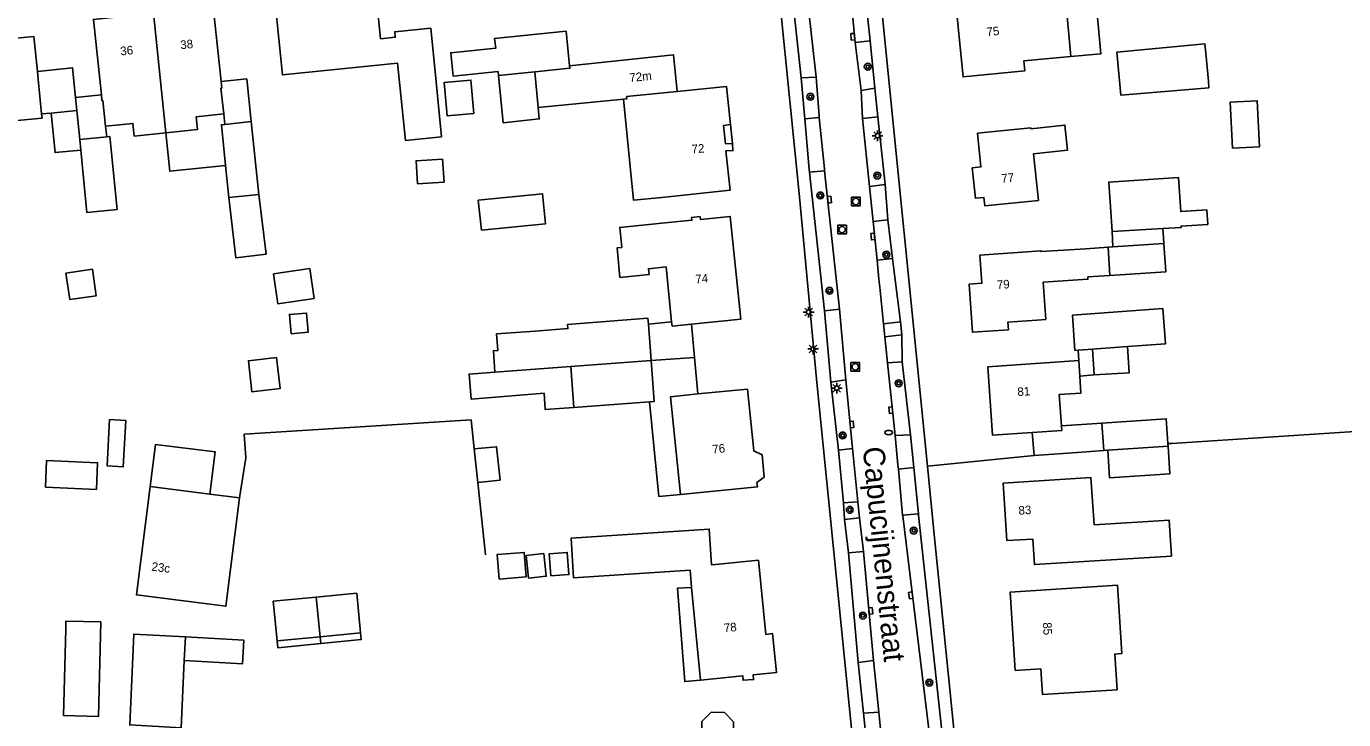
# Model space of a CAD drawing. Extents: x 140000 to 143000, y 403500 to 406000.
# Drawn here: x 140499.7 to 140652.7, y 403593.5 to 403674.1 of the extents above; entities that cross this region are included whole.
import ezdxf

# ---------------------------------------------------------------- set-up
doc = ezdxf.new("R2010")
doc.units = 0
for name, color, linetype in [('gg-afsc-erfafscheiding', 7, 'Continuous'), ('gg-afsc-hekwerk', 7, 'Continuous'), ('gg-anno-huisnummerreeks BGT', 7, 'Continuous'), ('gg-anno-openbare ruimte label', 7, 'Continuous'), ('gg-bbg-bijgebouw', 7, 'Continuous'), ('gg-bbg-gedigitaliseerde bebouwing', 7, 'Continuous'), ('gg-bbg-gedigitaliseerde bijgebouw', 7, 'Continuous'), ('gg-bbg-hoofdgebouw', 7, 'Continuous'), ('gg-bbg-luifel en loopbrug', 7, 'Continuous'), ('gg-bbg-overig bouwwerk', 7, 'Continuous'), ('gg-bbg-tussenscheiding', 7, 'Continuous'), ('gg-knt-verharding', 7, 'Continuous'), ('gg-knt-verharding nz', 7, 'Continuous'), ('gt-symb-boom', 7, 'Continuous'), ('gt-symb-brandkraan', 7, 'Continuous'), ('gt-symb-kolk', 7, 'Continuous'), ('gt-symb-lichtmast', 7, 'Continuous'), ('gt-symb-rioolschacht', 7, 'Continuous')]:
    doc.layers.add(name, color=color, linetype=linetype)

# ---------------------------------------------------------------- blocks, each defined once
blk = doc.blocks.new('gt0-KOLK')
at = {"layer": 'gt-symb-kolk'}
blk.add_lwpolyline([(0, 0), (0.38, 0), (0.38, 0.4), (-0.37, 0.4), (-0.37, 0), (0, 0)], dxfattribs=at)
blk = doc.blocks.new('gt0-BR')
at = {"layer": 'gt-symb-brandkraan'}
for centre, radius, start, end in [((-0.24, 0), 0.206, 107.5669, 252.4331), ((0.6, -2.66), 3, 106.892, 107.5669), ((0, -0.69), 0.938, 73.108, 106.892), ((-0.6, -2.66), 3, 72.4331, 73.108), ((0.24, 0), 0.206, 287.567, 72.4331), ((0.6, 2.66), 3, 252.4331, 253.108), ((0, 0.69), 0.938, 253.108, 286.8921), ((-0.6, 2.66), 3, 286.8921, 287.567)]:
    blk.add_arc(centre, radius, start, end, dxfattribs=at)
blk = doc.blocks.new('gt0-LMAST')
at = {"layer": 'gt-symb-lichtmast'}
for p, q in [((-0.18, 0.17), (-0.45, 0.44)), ((-0.01, 0.25), (-0.01, 0.62)), ((0.17, 0.17), (0.44, 0.44)), ((-0.26, 0), (-0.63, 0)), ((-0.18, -0.18), (-0.45, -0.45)), ((-0.01, -0.25), (-0.01, -0.63)), ((0.44, -0.45), (0.17, -0.18)), ((0.24, 0), (0.62, 0))]:
    blk.add_line(p, q, dxfattribs=at)
blk.add_circle((-0.01, 0), 0.25, dxfattribs=at)
blk = doc.blocks.new('gt0-BOOM')
at = {"layer": 'gt-symb-boom'}
for radius in [0.4, 0.2]:
    blk.add_circle((0, 0), radius, dxfattribs=at)
blk = doc.blocks.new('gt0-RS')
at = {"layer": 'gt-symb-rioolschacht'}
blk.add_lwpolyline([(-0.5, -0.5), (0.5, -0.5), (0.5, 0.5), (-0.5, 0.5)], close=True, dxfattribs=at)
blk.add_circle((0, 0), 0.375, dxfattribs=at)

msp = doc.modelspace()

# ---------------------------------------------------------------- linework, layer by layer
at = {"layer": 'gg-afsc-erfafscheiding'}
for p, q in [((140616.75, 403624.23), (140604.37, 403622.98)), ((140607.14, 403595.14), (140611, 403556.5))]:
    msp.add_line(p, q, dxfattribs=at)
for points in [[(140524.47, 403619.29), (140525.2, 403623.94), (140525, 403626.69), (140551.38, 403628.34)], [(140658.72, 403627.3), (140632.76, 403625.62), (140632.3, 403625.6)], [(140604.37, 403622.98), (140605.16, 403615.02), (140607.14, 403595.14)]]:
    msp.add_lwpolyline(points, dxfattribs=at)
at = {"layer": 'gg-afsc-hekwerk'}
for p, q in [((140551.38, 403628.34), (140551.73, 403624.97)), ((140552.13, 403621.09), (140553.01, 403612.66))]:
    msp.add_line(p, q, dxfattribs=at)
at = {"layer": 'gg-bbg-bijgebouw'}
for p, q in [((140554.53, 403668.36), (140558.74, 403668.79)), ((140505.56, 403664.3), (140502.58, 403664.01)), ((140505.9, 403660.93), (140505.56, 403664.3)), ((140525.82, 403663.01), (140522.75, 403662.68)), ((140526.71, 403654.56), (140525.82, 403663.01)), ((140505.9, 403660.93), (140509.03, 403661.24)), ((140523.23, 403654.2), (140522.84, 403657.92)), ((140523.23, 403654.2), (140526.71, 403654.56)), ((140625.8, 403650.25), (140625.91, 403648.45)), ((140631.82, 403648.84), (140625.91, 403648.45)), ((140572.27, 403635.26), (140571.95, 403639.46)), ((140627.59, 403636.87), (140623.54, 403636.57)), ((140562.93, 403634.56), (140554.12, 403633.89)), ((140562.93, 403634.56), (140563.29, 403629.79)), ((140563.29, 403629.79), (140572.08, 403630.46)), ((140624.85, 403624.81), (140624.63, 403627.98)), ((140624.85, 403624.81), (140625.3, 403624.84)), ((140632.3, 403625.6), (140632.32, 403625.31)), ((140518.17, 403603.14), (140518.04, 403600.38))]:
    msp.add_line(p, q, dxfattribs=at)
for points in [[(140562.8, 403669.49), (140562.39, 403673.51), (140554.09, 403672.66), (140554.21, 403671.54), (140549, 403671.01), (140549.28, 403668.3), (140554.49, 403668.83), (140554.53, 403668.36)], [(140637.06, 403666.95), (140626.84, 403666.08), (140626.78, 403666.52), (140626.36, 403671.1), (140636.59, 403672.04), (140636.69, 403670.95), (140636.99, 403667.72), (140637.06, 403666.95)], [(140551.68, 403663.94), (140551.34, 403667.83), (140548.24, 403667.56), (140548.58, 403663.67), (140551.68, 403663.94)], [(140506.02, 403659.71), (140503.03, 403659.41), (140502.58, 403664.01)], [(140522.75, 403662.68), (140522.35, 403662.64), (140522.84, 403657.92)], [(140506.02, 403659.71), (140506.73, 403652.45), (140510.24, 403652.8), (140509.4, 403661.28), (140509.03, 403661.24)], [(140625.8, 403650.25), (140625.42, 403655.98), (140633.52, 403656.52), (140633.78, 403652.55), (140636.8, 403652.75), (140636.91, 403651.07), (140633.83, 403650.87), (140633.84, 403650.72), (140631.72, 403650.6)], [(140631.72, 403650.6), (140631.74, 403650.13), (140631.82, 403648.84)], [(140627.59, 403636.87), (140632.02, 403637.19), (140631.71, 403641.29), (140621.2, 403640.51), (140621.5, 403636.42), (140621.85, 403636.44)], [(140530.44, 403638.37), (140532.43, 403638.53), (140532.25, 403640.77), (140530.25, 403640.61), (140530.44, 403638.37)], [(140571.95, 403639.46), (140571.9, 403640.16), (140562.56, 403639.45), (140562.6, 403638.96), (140558.79, 403638.67), (140554.31, 403638.34), (140554.46, 403636.43), (140553.94, 403636.39), (140554.12, 403633.89)], [(140572.08, 403630.46), (140572.63, 403630.5), (140572.27, 403635.26)], [(140624.63, 403627.98), (140632.1, 403628.49), (140632.3, 403625.6)], [(140625.3, 403624.84), (140625.51, 403621.61), (140632.53, 403622.09), (140632.32, 403625.31)], [(140501.92, 403620.53), (140507.84, 403620.28), (140507.97, 403623.38), (140502.05, 403623.63), (140501.92, 403620.53)], [(140508.34, 403604.89), (140504.29, 403604.98), (140504.27, 403604.03), (140504.03, 403593.99), (140508.08, 403593.89), (140508.34, 403604.89)], [(140518.17, 403603.14), (140512.18, 403603.47), (140511.7, 403592.9), (140517.68, 403592.56), (140518.04, 403600.38)], [(140578.11, 403591.79), (140579.18, 403590.68), (140580.71, 403590.66), (140581.81, 403591.72), (140581.83, 403593.25), (140580.77, 403594.36), (140579.24, 403594.38), (140578.14, 403593.32), (140578.11, 403591.79)]]:
    msp.add_lwpolyline(points, dxfattribs=at)
at = {"layer": 'gg-bbg-gedigitaliseerde bebouwing'}
for p, q in [((140521.02, 403619.73), (140514.08, 403620.6)), ((140524.47, 403619.29), (140521.02, 403619.73))]:
    msp.add_line(p, q, dxfattribs=at)
msp.add_lwpolyline([(140514.08, 403620.6), (140512.48, 403608.01), (140522.88, 403606.69), (140524.47, 403619.29)], dxfattribs=at)
at = {"layer": 'gg-bbg-gedigitaliseerde bijgebouw'}
for p, q in [((140621.93, 403635.24), (140621.85, 403636.44)), ((140623.74, 403633.57), (140623.54, 403636.57)), ((140623.74, 403633.57), (140622.05, 403633.45)), ((140551.73, 403624.97), (140552.13, 403621.09)), ((140538.07, 403608.23), (140533.37, 403607.77)), ((140538.52, 403603.61), (140538.07, 403608.23)), ((140528.83, 403602.66), (140533.83, 403603.15)), ((140533.83, 403603.15), (140538.52, 403603.61))]:
    msp.add_line(p, q, dxfattribs=at)
for points in [[(140528.77, 403635.59), (140525.49, 403635.22), (140525.9, 403631.61), (140529.17, 403631.98), (140528.77, 403635.59)], [(140552.13, 403621.09), (140554.72, 403621.35), (140554.32, 403625.23), (140551.73, 403624.97)], [(140533.37, 403607.77), (140528.37, 403607.28), (140528.83, 403602.66)]]:
    msp.add_lwpolyline(points, dxfattribs=at)
at = {"layer": 'gg-bbg-hoofdgebouw'}
for p, q in [((140621.01, 403670.57), (140620.4, 403677.38)), ((140559.15, 403664.65), (140558.74, 403668.79)), ((140569.04, 403665.62), (140559.15, 403664.65)), ((140625.55, 403645.13), (140625.34, 403648.41)), ((140619.96, 403627.12), (140619.92, 403627.66)), ((140616.54, 403626.88), (140619.96, 403627.12)), ((140576.94, 403608.89), (140578.01, 403598.12))]:
    msp.add_line(p, q, dxfattribs=at)
for points in [[(140528.58, 403676.8), (140529.43, 403668.44), (140542.8, 403669.81), (140543.07, 403667.19), (140543.73, 403660.82), (140547.9, 403661.25), (140547.29, 403667.62), (140546.67, 403673.87), (140542.49, 403673.46), (140542.55, 403672.81), (140540.85, 403672.64), (140540.19, 403679.28), (140535.62, 403678.82)], [(140514.45, 403675.61), (140521.41, 403676.34), (140522.32, 403667.67)], [(140620.4, 403677.38), (140619.39, 403677.25), (140614.88, 403676.8), (140614.85, 403677.05), (140607.69, 403676.33), (140608.5, 403668.2), (140615.66, 403668.92), (140615.55, 403670.07), (140621.01, 403670.57)], [(140514.45, 403675.61), (140507.49, 403674.89), (140508.41, 403666.11)], [(140500.99, 403668.85), (140500.56, 403672.91), (140496.17, 403672.46), (140496.23, 403671.96), (140489.53, 403671.3), (140490.4, 403662.35), (140501.52, 403663.43), (140501.47, 403663.9)], [(140575.29, 403666.51), (140574.86, 403670.78), (140562.8, 403669.49)], [(140501.47, 403663.9), (140501.08, 403667.94), (140500.99, 403668.85)], [(140522.62, 403663.92), (140522.3, 403666.9), (140522.4, 403666.91), (140522.32, 403667.67)], [(140581.49, 403662.66), (140581.04, 403667.08), (140575.29, 403666.51)], [(140508.41, 403666.11), (140508.48, 403665.45), (140508.58, 403665.46), (140508.9, 403662.47)], [(140569.04, 403665.62), (140570.22, 403653.88), (140573.5, 403654.21), (140581.46, 403655.06), (140580.96, 403659.6), (140581.77, 403659.65), (140581.71, 403660.48)], [(140515.89, 403661.72), (140512.23, 403661.33), (140512.08, 403662.81), (140508.9, 403662.47)], [(140515.89, 403661.72), (140519.58, 403662.11), (140519.43, 403663.58), (140522.62, 403663.92)], [(140581.71, 403660.48), (140580.91, 403660.42), (140580.68, 403662.58), (140581.49, 403662.66)], [(140617.27, 403653.86), (140616.69, 403659.28), (140620.63, 403659.71), (140620.32, 403662.61), (140616.37, 403662.18), (140616.36, 403662.29), (140610.17, 403661.66), (140610.57, 403657.74), (140609.57, 403657.64), (140609.93, 403654.1), (140610.93, 403654.21), (140611.03, 403653.21), (140617.27, 403653.86)], [(140576.95, 403639.47), (140582.67, 403640.04), (140581.46, 403652), (140578, 403651.65), (140577.96, 403651.98), (140576.97, 403651.88), (140577, 403651.55), (140573.5, 403651.2), (140568.63, 403650.71), (140568.87, 403648.39), (140568.31, 403648.33), (140568.65, 403644.91), (140572.03, 403645.25), (140571.96, 403645.92), (140574.01, 403646.13), (140574.65, 403639.73)], [(140625.34, 403648.41), (140622.77, 403648.24), (140617.56, 403647.9), (140617.55, 403648.01), (140610.46, 403647.51), (140610.69, 403644.22), (140609.19, 403644.12), (140609.58, 403638.53), (140613.77, 403638.82), (140613.71, 403639.72), (140617.07, 403639.95), (140618.1, 403640.02), (140617.81, 403644.35), (140623.01, 403644.7), (140622.99, 403644.97), (140625.55, 403645.13)], [(140574.65, 403639.73), (140574.7, 403639.25), (140576.95, 403639.47)], [(140621.93, 403635.24), (140616.37, 403634.86), (140611.38, 403634.52), (140611.93, 403626.56), (140616.54, 403626.88)], [(140619.92, 403627.66), (140619.68, 403631.29), (140622.18, 403631.46), (140622.05, 403633.45)], [(140575.67, 403619.68), (140584.61, 403620.57), (140584.56, 403621.07), (140585.4, 403621.7), (140585.17, 403624.28), (140584.19, 403624.74), (140583.46, 403631.94), (140577.69, 403631.37)], [(140577.69, 403631.37), (140574.53, 403631.05), (140575.67, 403619.68)], [(140632.71, 403612.5), (140632.45, 403616.69), (140623.71, 403616.16), (140623.34, 403621.65), (140613.14, 403620.99), (140613.59, 403614.33), (140616.59, 403614.5), (140616.78, 403611.53), (140632.71, 403612.5)], [(140578.01, 403598.12), (140582.9, 403598.61), (140582.95, 403598.1), (140584.16, 403598.18), (140584.12, 403598.73), (140586.83, 403599), (140586.38, 403603.51), (140585.59, 403603.43), (140584.73, 403612.05), (140579.76, 403611.55), (140579.29, 403611.5), (140579.01, 403615.66), (140562.96, 403614.6), (140563.26, 403609.99), (140576.8, 403610.89), (140576.94, 403608.89)], [(140614.56, 403599.24), (140617.53, 403599.43), (140617.73, 403596.43), (140626.39, 403596.99), (140626.12, 403601.14), (140626.93, 403601.19), (140626.42, 403609.15), (140613.97, 403608.35), (140614.56, 403599.24)]]:
    msp.add_lwpolyline(points, dxfattribs=at)
at = {"layer": 'gg-bbg-luifel en loopbrug'}
for p, q in [((140508.41, 403666.11), (140505.41, 403665.8)), ((140505.56, 403664.3), (140505.41, 403665.8)), ((140501.47, 403663.9), (140502.58, 403664.01)), ((140508.9, 403662.47), (140509.03, 403661.24)), ((140522.62, 403663.92), (140522.75, 403662.68)), ((140581.71, 403660.48), (140581.49, 403662.66)), ((140625.34, 403648.41), (140625.91, 403648.45)), ((140574.65, 403639.73), (140571.95, 403639.46)), ((140576.95, 403639.47), (140577.3, 403635.59)), ((140572.27, 403635.26), (140577.3, 403635.59)), ((140577.69, 403631.37), (140577.3, 403635.59)), ((140619.92, 403627.66), (140624.63, 403627.98)), ((140616.54, 403626.88), (140616.75, 403624.23)), ((140616.75, 403624.23), (140620.14, 403624.46)), ((140533.83, 403603.15), (140533.9, 403602.36))]:
    msp.add_line(p, q, dxfattribs=at)
for points in [[(140621.01, 403670.57), (140624.49, 403670.88), (140623.88, 403677.69), (140620.4, 403677.38)], [(140500.99, 403668.85), (140505.07, 403669.28), (140505.41, 403665.8)], [(140522.32, 403667.67), (140525.3, 403667.98), (140525.82, 403663.01)], [(140554.53, 403668.36), (140555.09, 403662.89), (140559.28, 403663.32), (140559.15, 403664.65)], [(140515.89, 403661.72), (140516.36, 403657.24), (140522.84, 403657.92)], [(140523.23, 403654.2), (140524.03, 403647.19), (140527.55, 403647.62), (140526.71, 403654.56)], [(140552.55, 403650.39), (140560.01, 403651.15), (140559.65, 403654.63), (140552.19, 403653.87), (140552.55, 403650.39)], [(140625.55, 403645.13), (140632.04, 403645.56), (140631.82, 403648.84)], [(140507.37, 403645.85), (140504.3, 403645.4), (140504.75, 403642.34), (140507.82, 403642.78), (140507.37, 403645.85)], [(140528.4, 403645.34), (140528.9, 403641.85), (140533.12, 403642.45), (140532.62, 403645.94), (140528.4, 403645.34)], [(140623.74, 403633.57), (140627.8, 403633.82), (140627.59, 403636.87)], [(140563.29, 403629.79), (140559.97, 403629.54), (140559.83, 403631.44), (140551.35, 403630.77), (140551.13, 403633.67), (140554.12, 403633.89)], [(140572.08, 403630.46), (140573.18, 403619.43), (140575.67, 403619.68)], [(140514.08, 403620.6), (140514.7, 403625.51), (140521.64, 403624.63), (140521.02, 403619.73)], [(140620.14, 403624.46), (140621.74, 403624.57), (140624.85, 403624.81)], [(140554.6, 403609.85), (140557.75, 403610.1), (140557.52, 403612.95), (140554.37, 403612.69), (140554.6, 403609.85)], [(140576.94, 403608.89), (140575.32, 403608.78), (140576.17, 403597.94), (140578.01, 403598.12)], [(140518.17, 403603.14), (140524.95, 403602.76), (140524.8, 403600), (140518.04, 403600.38)], [(140533.9, 403602.36), (140538.6, 403602.83), (140538.52, 403603.61)], [(140528.83, 403602.66), (140528.9, 403601.88), (140533.9, 403602.36)]]:
    msp.add_lwpolyline(points, dxfattribs=at)
at = {"layer": 'gg-bbg-overig bouwwerk'}
for points in [[(140639.79, 403659.92), (140642.93, 403660.07), (140642.67, 403665.43), (140639.53, 403665.28), (140639.79, 403659.92)], [(140548.03, 403658.66), (140544.96, 403658.46), (140545.14, 403655.78), (140548.21, 403655.99), (140548.03, 403658.66)], [(140511.25, 403628.29), (140509.36, 403628.39), (140509.07, 403623.02), (140510.96, 403622.91), (140511.25, 403628.29)], [(140558.04, 403609.97), (140560.08, 403610.19), (140559.79, 403612.81), (140557.75, 403612.59), (140558.04, 403609.97)], [(140560.63, 403610.22), (140562.71, 403610.37), (140562.53, 403612.95), (140560.44, 403612.8), (140560.63, 403610.22)]]:
    msp.add_lwpolyline(points, dxfattribs=at)
at = {"layer": 'gg-bbg-tussenscheiding'}
for p, q in [((140515.89, 403661.72), (140514.45, 403675.61)), ((140505.9, 403660.93), (140506.02, 403659.71)), ((140625.8, 403650.25), (140631.72, 403650.6)), ((140623.54, 403636.57), (140621.85, 403636.44)), ((140572.27, 403635.26), (140562.93, 403634.56)), ((140622.05, 403633.45), (140621.93, 403635.24)), ((140533.37, 403607.77), (140533.83, 403603.15))]:
    msp.add_line(p, q, dxfattribs=at)
for points in [[(140558.74, 403668.79), (140562.83, 403669.21), (140562.8, 403669.49)], [(140575.29, 403666.51), (140569.42, 403665.92), (140569.45, 403665.66), (140569.04, 403665.62)], [(140625.3, 403624.84), (140630.57, 403625.19), (140632.32, 403625.31)]]:
    msp.add_lwpolyline(points, dxfattribs=at)
at = {"layer": 'gg-knt-verharding'}
for p, q in [((140604.37, 403622.98), (140559.76, 404069.98)), ((140597.07, 403678.49), (140597.72, 403672.39)), ((140589.69, 403668.11), (140588.81, 403676.3)), ((140597.72, 403672.39), (140595.95, 403672.19)), ((140596.65, 403666.64), (140595.95, 403672.19)), ((140597.72, 403672.39), (140598.26, 403666.89)), ((140589.69, 403668.11), (140591.45, 403668.19)), ((140590.11, 403663.35), (140589.69, 403668.11)), ((140598.26, 403666.89), (140596.65, 403666.64)), ((140598.26, 403666.89), (140598.59, 403663.58)), ((140590.11, 403663.35), (140591.79, 403663.5)), ((140598.59, 403663.58), (140596.8, 403663.37)), ((140597.62, 403655.46), (140596.8, 403663.37)), ((140598.59, 403663.58), (140599.45, 403655.69)), ((140590.67, 403657.14), (140592.42, 403657.31)), ((140592.4, 403641.04), (140590.67, 403657.14)), ((140592.42, 403657.31), (140594.16, 403641.23)), ((140599.45, 403655.69), (140597.62, 403655.46)), ((140599.45, 403655.69), (140599.77, 403651.58)), ((140599.77, 403651.58), (140598.04, 403651.41)), ((140598.51, 403646.9), (140598.04, 403651.41)), ((140599.77, 403651.58), (140600.3, 403647.11)), ((140600.3, 403647.11), (140598.51, 403646.9)), ((140592.4, 403641.04), (140594.16, 403641.23)), ((140593.13, 403632.73), (140592.4, 403641.04)), ((140601.22, 403639.75), (140599.27, 403639.51)), ((140599.43, 403638.01), (140599.27, 403639.51)), ((140601.22, 403639.75), (140601.38, 403638.23)), ((140601.38, 403638.23), (140599.43, 403638.01)), ((140601.38, 403638.23), (140601.43, 403635.11)), ((140601.43, 403635.11), (140599.74, 403634.97)), ((140600.62, 403626.52), (140599.74, 403634.97)), ((140601.43, 403635.11), (140602.39, 403626.63)), ((140593.13, 403632.73), (140594.89, 403632.99)), ((140594.04, 403624.85), (140593.13, 403632.73)), ((140594.89, 403632.99), (140595.66, 403625.04)), ((140602.39, 403626.63), (140600.62, 403626.52)), ((140602.39, 403626.63), (140602.77, 403622.82)), ((140594.04, 403624.85), (140595.66, 403625.04)), ((140594.62, 403618.72), (140594.04, 403624.85)), ((140602.77, 403622.82), (140600.98, 403622.64)), ((140602.77, 403622.82), (140603.32, 403617.43)), ((140594.62, 403618.72), (140596.29, 403618.81)), ((140594.73, 403616.79), (140594.62, 403618.72)), ((140596.29, 403618.81), (140596.47, 403616.98)), ((140594.73, 403616.79), (140596.47, 403616.98)), ((140595.2, 403612.92), (140594.73, 403616.79)), ((140603.32, 403617.43), (140601.48, 403617.28)), ((140595.2, 403612.92), (140596.92, 403613.06)), ((140596.3, 403600.14), (140595.2, 403612.92)), ((140596.92, 403613.06), (140598.11, 403600.38)), ((140596.3, 403600.14), (140598.11, 403600.38)), ((140596.92, 403594.26), (140596.3, 403600.14)), ((140596.92, 403594.26), (140598.71, 403594.39)), ((140601.72, 403564.17), (140598.71, 403594.39))]:
    msp.add_line(p, q, dxfattribs=at)
for points in [[(140586.17, 403687.39), (140589.45, 403654.67), (140591.51, 403632.7), (140593.79, 403609.93), (140596.7, 403580.82)], [(140591.79, 403663.5), (140591.77, 403663.67), (140591.45, 403668.19)], [(140590.67, 403657.14), (140590.63, 403657.44), (140590.11, 403663.35)], [(140600.3, 403647.11), (140600.56, 403644.92), (140601.22, 403639.75)], [(140605.22, 403586.66), (140601.49, 403617.19), (140601.48, 403617.28)], [(140603.32, 403617.43), (140603.34, 403617.27), (140606.62, 403586.84)], [(140601.72, 403564.17), (140600.09, 403563.95), (140596.92, 403594.26)]]:
    msp.add_lwpolyline(points, dxfattribs=at)
at = {"layer": 'gg-knt-verharding nz'}
for p, q in [((140595.95, 403672.19), (140595.39, 403678.45)), ((140590.49, 403676.48), (140591.45, 403668.19)), ((140596.8, 403663.37), (140596.65, 403666.64)), ((140598.04, 403651.41), (140597.62, 403655.46)), ((140594.16, 403641.23), (140594.89, 403632.99)), ((140599.74, 403634.97), (140599.43, 403638.01)), ((140595.66, 403625.04), (140596.29, 403618.81)), ((140601.48, 403617.28), (140600.98, 403622.64)), ((140596.47, 403616.98), (140596.92, 403613.06)), ((140598.11, 403600.38), (140598.71, 403594.39))]:
    msp.add_line(p, q, dxfattribs=at)
for points in [[(140592.42, 403657.31), (140592.4, 403657.54), (140591.79, 403663.5)], [(140599.27, 403639.51), (140598.83, 403643.76), (140598.73, 403644.71), (140598.51, 403646.9)], [(140600.98, 403622.64), (140600.93, 403623.14), (140600.62, 403626.52)]]:
    msp.add_lwpolyline(points, dxfattribs=at)

# ---------------------------------------------------------------- block references
at = {"layer": 'gt-symb-boom'}
for p in [(140597.43, 403669.39), (140590.77, 403665.9), (140598.53, 403656.74), (140591.92, 403654.43), (140599.59, 403647.56), (140592.98, 403643.36), (140601.02, 403632.61), (140594.51, 403626.54), (140595.34, 403617.9), (140602.77, 403615.49), (140596.86, 403605.61), (140604.58, 403597.82)]:
    msp.add_blockref('gt0-BOOM', p, dxfattribs=at)
at = {"layer": 'gt-symb-brandkraan'}
msp.add_blockref('gt0-BR', (140599.86, 403626.88), dxfattribs=at)
at = {"layer": 'gt-symb-kolk'}
for p, rotation in [((140595.88, 403672.89), 95.01762672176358), ((140592.79, 403653.93), -83.81486364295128), ((140598.22, 403649.67), 95.91776668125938), ((140600.31, 403629.49), 95.90973955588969), ((140595.39, 403627.81), -84.4227086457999), ((140602.61, 403607.98), 96.9568648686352), ((140597.57, 403606.14), -84.61781256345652)]:
    msp.add_blockref('gt0-KOLK', p, dxfattribs=dict(at, rotation=rotation))
at = {"layer": 'gt-symb-lichtmast'}
for p in [(140598.57, 403661.37), (140590.57, 403640.88), (140591.08, 403636.59), (140593.83, 403632.04)]:
    msp.add_blockref('gt0-LMAST', p, dxfattribs=at)
at = {"layer": 'gt-symb-rioolschacht'}
for p in [(140596.05, 403653.73), (140594.44, 403650.46), (140595.98, 403634.51)]:
    msp.add_blockref('gt0-RS', p, dxfattribs=at)

# ---------------------------------------------------------------- texts
at = {"layer": 'gg-anno-huisnummerreeks BGT'}
for s, rotation, p in [('75', 5.7, (140611.27, 403672.93)), ('36', 5.9, (140510.66, 403670.7)), ('38', 5.9, (140517.63, 403671.42)), ('72m', 5.7, (140569.79, 403667.61)), ('72', 4, (140577, 403659.32)), ('77', 5.8, (140612.99, 403655.9)), ('74', 5.7, (140577.45, 403644.2)), ('79', 3.9, (140612.46, 403643.55)), ('81', 3.9, (140614.84, 403631.11)), ('76', 5.7, (140579.42, 403624.43)), ('83', 3.6, (140614.97, 403617.32)), ('23c', 352.8, (140514.19, 403610.84)), ('78', 5.7, (140580.76, 403603.67)), ('85', 273.7, (140617.76, 403604.8))]:
    msp.add_text(s, height=1, rotation=rotation, dxfattribs=at).set_placement(p)
at = {"layer": 'gg-anno-openbare ruimte label'}
msp.add_text('Capucijnenstraat', height=2.5, rotation=275.7, dxfattribs=at).set_placement((140596.84, 403625.12))

doc.saveas('drawing.dxf')
